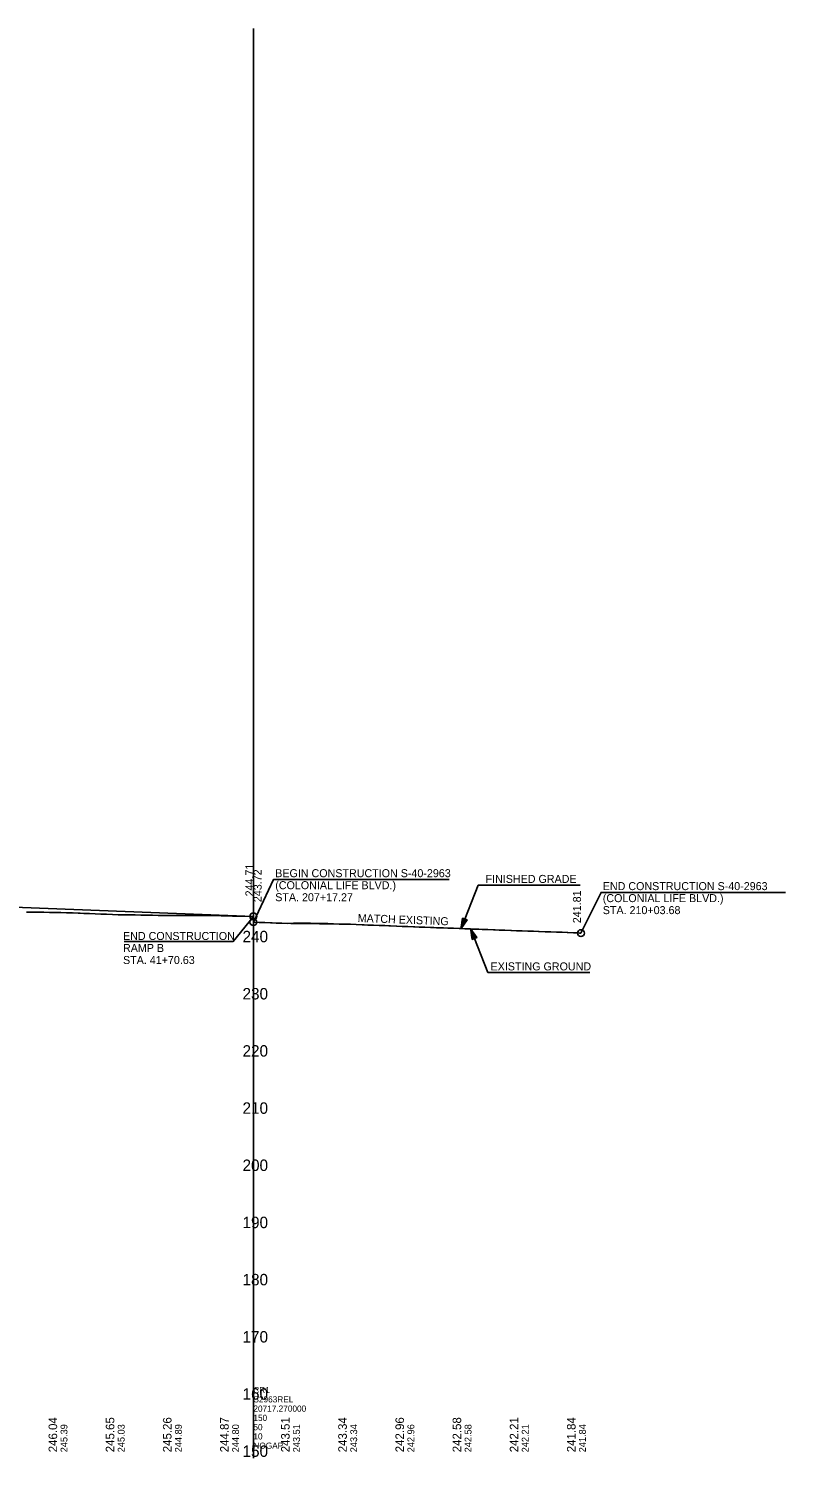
# Model space of a CAD drawing. Extents: x 69 to 2003113, y 512 to 837401.
# Drawn here: x 1926146 to 1926808, y 792663 to 793913 of the extents above; entities that cross this region are included whole.
import ezdxf

# ---------------------------------------------------------------- set-up
doc = ezdxf.new("R2010")
doc.units = 0
for name, color, linetype in [('BR_BORDER LINES', 7, 'Continuous'), ('BR_CENTER LINE BASELINE', 7, 'Continuous'), ('BR_CONCRETE', 7, 'Continuous'), ('BR_GRID DOTS', 7, 'Continuous'), ('BR_GRID LINES', 7, 'Continuous'), ('BR_TEXT', 7, 'Continuous'), ('MISCELLANEOUS', 7, 'Continuous'), ('RD_HC_Points', 7, 'Continuous'), ('RD_PD_ALT1_TrvlWay', 7, 'Continuous'), ('RD_SHT_IplotShp', 7, 'Continuous')]:
    doc.layers.add(name, color=color, linetype=linetype)

msp = doc.modelspace()

# ---------------------------------------------------------------- linework, layer by layer
at = {"layer": 'BR_BORDER LINES'}
msp.add_line((1926343, 792662.9), (1926343, 793912.9), dxfattribs=at)
at = {"layer": 'BR_CENTER LINE BASELINE'}
msp.add_line((1926185.4, 793139.6), (1926191.4, 793139.4), dxfattribs=at)
for centre in [(1926343, 793136.5), (1926343, 793131.5), (1926629.4, 793121.9)]:
    msp.add_circle(centre, 3, dxfattribs=at)
at = {"layer": 'BR_GRID DOTS'}
for points in [[(1926343, 793131.5), (1926360.6, 793168.9), (1926514.2, 793168.9)], [(1926629.4, 793121.9), (1926647, 793157.5), (1926808.2, 793157.5)], [(1926343, 793136.5), (1926325.4, 793114.7), (1926229.9, 793114.7)]]:
    msp.add_lwpolyline(points, dxfattribs=at)
at = {"layer": 'BR_GRID LINES'}
msp.add_line((1926118.4, 793145.2), (1926343, 793136.5), dxfattribs=at)
msp.add_lwpolyline([(1926343, 793131.5), (1926375.7, 793130.4), (1926425.7, 793129.6), (1926475.7, 793127.7), (1926525.7, 793125.8), (1926575.7, 793123.9), (1926625.7, 793122.1), (1926629.4, 793121.9)], dxfattribs=at)
at = {"layer": 'BR_TEXT'}
for points in [[(1926144.7, 793140.3), (1926149.7, 793140.2), (1926154.7, 793140.2), (1926159.7, 793140.1), (1926164.7, 793140), (1926169.7, 793139.9), (1926174.7, 793139.8), (1926179.7, 793139.6), (1926184.7, 793139.5), (1926189.7, 793139.3), (1926194.7, 793139.2), (1926199.7, 793139), (1926204.7, 793138.9), (1926209.7, 793138.6), (1926214.7, 793138.4), (1926219.7, 793138.2), (1926224.7, 793138), (1926229.7, 793137.9), (1926234.7, 793138), (1926239.7, 793137.8), (1926244.7, 793137.6), (1926249.7, 793137.5), (1926254.7, 793137.6), (1926259.7, 793137.3), (1926264.7, 793137.4), (1926269.7, 793137.4), (1926274.7, 793137.3), (1926279.7, 793137.3), (1926284.7, 793137.3), (1926289.7, 793137.4), (1926294.7, 793137.4), (1926299.7, 793137.4), (1926304.7, 793137.3), (1926309.7, 793137.2), (1926314.7, 793137.1), (1926319.7, 793137), (1926324.7, 793136.8), (1926329.7, 793136.7), (1926334.7, 793136.6), (1926339.7, 793136.5), (1926343, 793136.4)], [(1926343, 793131.5), (1926348, 793131.3), (1926353, 793131.1), (1926358, 793130.9), (1926363, 793130.7), (1926368, 793130.6), (1926373, 793130.4), (1926378, 793130.5), (1926383, 793130.6), (1926388, 793130.6), (1926393, 793130.6), (1926398, 793130.4), (1926403, 793130.3), (1926408, 793130.2), (1926413, 793129.9), (1926418, 793129.8), (1926423, 793129.7), (1926428, 793129.6), (1926433, 793129.4), (1926438, 793129.2), (1926443, 793129), (1926448, 793128.9), (1926453, 793128.7), (1926458, 793128.5), (1926463, 793128.3), (1926468, 793128), (1926473, 793127.8), (1926478, 793127.6), (1926483, 793127.4), (1926488, 793127.2), (1926493, 793127), (1926498, 793126.8), (1926503, 793126.6), (1926508, 793126.4), (1926513, 793126.2), (1926518, 793126.1), (1926523, 793125.9), (1926528, 793125.7), (1926533, 793125.5), (1926538, 793125.3), (1926543, 793125.1), (1926548, 793125), (1926553, 793124.8), (1926558, 793124.6), (1926563, 793124.4), (1926568, 793124.2), (1926573, 793124), (1926578, 793123.8), (1926583, 793123.6), (1926588, 793123.5), (1926593, 793123.3), (1926598, 793123.1), (1926603, 793122.9), (1926608, 793122.7), (1926613, 793122.7), (1926618, 793122.5), (1926623, 793122.2), (1926628, 793122), (1926629.4, 793121.9)]]:
    msp.add_lwpolyline(points, dxfattribs=at)
at = {"layer": 'RD_PD_ALT1_TrvlWay'}
for p, q in [((1926524.6, 793125.8), (1926539.6, 793163.8)), ((1926539.6, 793163.8), (1926628.7, 793163.8)), ((1926524.6, 793125.8), (1926525.8, 793135)), ((1926527.9, 793134.2), (1926524.6, 793125.8)), ((1926524.6, 793125.8), (1926530, 793133.4)), ((1926525.8, 793135), (1926530, 793133.4)), ((1926533, 793125.5), (1926548, 793087.5)), ((1926536.3, 793117.1), (1926533, 793125.5)), ((1926533, 793125.5), (1926538.4, 793118)), ((1926533, 793125.5), (1926534.2, 793116.3)), ((1926534.2, 793116.3), (1926538.4, 793118)), ((1926548, 793087.5), (1926637.1, 793087.5))]:
    msp.add_line(p, q, dxfattribs=at)
for points in [[(1926527.8, 793134.1), (1926524.7, 793126.3), (1926527.8, 793134.2), (1926524.8, 793126.7), (1926527.7, 793134.2), (1926524.8, 793127), (1926527.5, 793134.2), (1926524.8, 793127.3), (1926527.5, 793134.3), (1926524.9, 793127.8), (1926527.4, 793134.3), (1926525, 793128.3), (1926527.2, 793134.3), (1926525.1, 793128.7), (1926527.2, 793134.4), (1926525.1, 793129.2), (1926527.1, 793134.4), (1926525.2, 793129.6), (1926527, 793134.5), (1926525.2, 793129.9), (1926526.9, 793134.5), (1926525.3, 793130.4), (1926526.8, 793134.6), (1926525.4, 793131), (1926526.7, 793134.6), (1926525.4, 793131.4), (1926526.6, 793134.6), (1926525.5, 793132.1), (1926526.4, 793134.7), (1926525.6, 793132.6), (1926526.3, 793134.8), (1926525.6, 793133), (1926526.2, 793134.8), (1926525.7, 793133.4), (1926526.2, 793134.8), (1926525.7, 793133.9), (1926526, 793134.8), (1926525.8, 793134.5), (1926525.9, 793134.8)], [(1926524.9, 793126.3), (1926527.9, 793134.1), (1926525, 793126.6), (1926528, 793134), (1926525.2, 793126.8), (1926528.1, 793134), (1926525.4, 793127.1), (1926528.2, 793134), (1926525.6, 793127.3), (1926528.3, 793134), (1926525.7, 793127.6), (1926528.3, 793134), (1926526, 793127.9), (1926528.4, 793133.9), (1926526.2, 793128.2), (1926528.5, 793133.9), (1926526.4, 793128.5), (1926528.6, 793133.9), (1926526.6, 793128.9), (1926528.7, 793133.8), (1926526.9, 793129.2), (1926528.8, 793133.8), (1926527.1, 793129.5), (1926528.8, 793133.7), (1926527.4, 793130), (1926528.9, 793133.7), (1926527.7, 793130.3), (1926529, 793133.7), (1926528, 793130.7), (1926529.1, 793133.7), (1926528.2, 793131.1), (1926529.2, 793133.6), (1926528.4, 793131.4), (1926529.3, 793133.5), (1926528.7, 793131.7), (1926529.3, 793133.5), (1926529, 793132.1), (1926529.5, 793133.5), (1926529.1, 793132.4), (1926529.6, 793133.4), (1926529.3, 793132.6), (1926529.7, 793133.3), (1926529.8, 793133.4), (1926529.7, 793133.3)], [(1926536.2, 793117.2), (1926533.1, 793125), (1926536.2, 793117.1), (1926533.2, 793124.6), (1926536.1, 793117.1), (1926533.2, 793124.3), (1926536, 793117.1), (1926533.3, 793124), (1926535.9, 793117.1), (1926533.3, 793123.5), (1926535.8, 793117), (1926533.4, 793123), (1926535.6, 793117), (1926533.5, 793122.6), (1926535.6, 793116.9), (1926533.5, 793122.1), (1926535.5, 793117), (1926533.6, 793121.7), (1926535.4, 793116.9), (1926533.6, 793121.4), (1926535.3, 793116.8), (1926533.7, 793120.9), (1926535.2, 793116.8), (1926533.8, 793120.3), (1926535.1, 793116.7), (1926533.8, 793119.9), (1926535, 793116.7), (1926533.9, 793119.3), (1926534.8, 793116.7), (1926534, 793118.8), (1926534.7, 793116.6), (1926534, 793118.3), (1926534.6, 793116.6), (1926534.1, 793117.9), (1926534.6, 793116.5), (1926534.2, 793117.4), (1926534.4, 793116.5), (1926534.2, 793116.9), (1926534.3, 793116.5)], [(1926533.3, 793125), (1926536.3, 793117.3), (1926533.4, 793124.7), (1926536.4, 793117.3), (1926533.6, 793124.5), (1926536.5, 793117.3), (1926533.8, 793124.3), (1926536.6, 793117.3), (1926534, 793124), (1926536.7, 793117.4), (1926534.2, 793123.8), (1926536.7, 793117.4), (1926534.4, 793123.5), (1926536.8, 793117.4), (1926534.6, 793123.1), (1926536.9, 793117.5), (1926534.8, 793122.8), (1926537, 793117.5), (1926535, 793122.5), (1926537.1, 793117.5), (1926535.3, 793122.2), (1926537.2, 793117.5), (1926535.5, 793121.8), (1926537.2, 793117.6), (1926535.8, 793121.4), (1926537.3, 793117.6), (1926536.1, 793121.1), (1926537.4, 793117.6), (1926536.4, 793120.7), (1926537.5, 793117.7), (1926536.6, 793120.3), (1926537.6, 793117.7), (1926536.8, 793120), (1926537.7, 793117.8), (1926537.1, 793119.7), (1926537.7, 793117.9), (1926537.4, 793119.2), (1926537.9, 793117.8), (1926537.6, 793118.9), (1926538, 793117.9), (1926537.7, 793118.8), (1926538.1, 793118), (1926538.3, 793118), (1926538.1, 793118)]]:
    msp.add_lwpolyline(points, dxfattribs=at)

# ---------------------------------------------------------------- texts
at = {"layer": 'BR_BORDER LINES'}
for s, p in [('CR1', (1926343, 792719.6)), ('S2963REL', (1926343, 792711.5)), ('20717.270000', (1926343, 792703.4)), ('150', (1926343, 792695.3)), ('50', (1926343, 792687.2)), ('10', (1926343, 792679.1)), ('NOGAP', (1926343, 792671))]:
    msp.add_text(s, height=5.4, dxfattribs=at).set_placement(p)
at = {"layer": 'BR_CENTER LINE BASELINE'}
msp.add_text('MATCH EXISTING', height=7, rotation=357.8354, dxfattribs=at).set_placement((1926434.1, 793131.7))
at = {"layer": 'BR_CONCRETE'}
for s, p in [('245.39', (1926180.4, 792667.9)), ('245.03', (1926230.4, 792667.9)), ('244.89', (1926280.4, 792667.9)), ('244.80', (1926330.4, 792667.9)), ('243.51', (1926383.7, 792667.9)), ('243.34', (1926433.7, 792667.9)), ('242.96', (1926483.7, 792667.9)), ('242.58', (1926533.7, 792667.9)), ('242.21', (1926583.7, 792667.9)), ('241.84', (1926633.7, 792667.9))]:
    msp.add_text(s, height=6, rotation=90, dxfattribs=at).set_placement(p)
at = {"layer": 'MISCELLANEOUS'}
for s, p in [('240', (1926333.5, 793113.9)), ('230', (1926333.5, 793063.9)), ('220', (1926333.5, 793013.9)), ('210', (1926333.5, 792963.9)), ('200', (1926333.5, 792913.9)), ('190', (1926333.5, 792863.9)), ('180', (1926333.5, 792813.9)), ('170', (1926333.5, 792763.9)), ('160', (1926333.5, 792713.9)), ('150', (1926333.5, 792663.9))]:
    msp.add_text(s, height=10, dxfattribs=at).set_placement(p)
at = {"layer": 'RD_HC_Points'}
for s, p in [('246.04', (1926171.4, 792667.9)), ('245.65', (1926221.4, 792667.9)), ('245.26', (1926271.4, 792667.9)), ('244.87', (1926321.4, 792667.9)), ('243.51', (1926374.7, 792667.9)), ('243.34', (1926424.7, 792667.9)), ('242.96', (1926474.7, 792667.9)), ('242.58', (1926524.7, 792667.9)), ('242.21', (1926574.7, 792667.9)), ('241.84', (1926624.7, 792667.9))]:
    msp.add_text(s, height=7.5, rotation=90, dxfattribs=at).set_placement(p)
at = {"layer": 'RD_PD_ALT1_TrvlWay'}
for s, p in [('FINISHED GRADE', (1926546, 793165.8)), ('EXISTING GROUND', (1926550.4, 793089.3))]:
    msp.add_text(s, height=7, dxfattribs=at).set_placement(p)
at = {"layer": 'RD_SHT_IplotShp'}
for s, p in [('244.71', (1926343, 793154)), ('243.72', (1926350.2, 793149)), ('241.81', (1926629.4, 793130.6))]:
    msp.add_text(s, height=7, rotation=90, dxfattribs=at).set_placement(p)
for s, p in [('BEGIN CONSTRUCTION S-40-2963', (1926362.1, 793170.8)), ('STA. 207+17.27', (1926362.1, 793149.8)), ('(COLONIAL LIFE BLVD.)', (1926362.1, 793160.3)), ('(COLONIAL LIFE BLVD.) ', (1926648.5, 793149)), ('END CONSTRUCTION S-40-2963', (1926648.5, 793159.5)), ('STA. 210+03.68', (1926648.5, 793138.5)), ('END CONSTRUCTION', (1926229, 793115.9)), ('RAMP B ', (1926229, 793105.4)), ('STA. 41+70.63', (1926229, 793094.9))]:
    msp.add_text(s, height=7, dxfattribs=at).set_placement(p)

doc.saveas('drawing.dxf')
